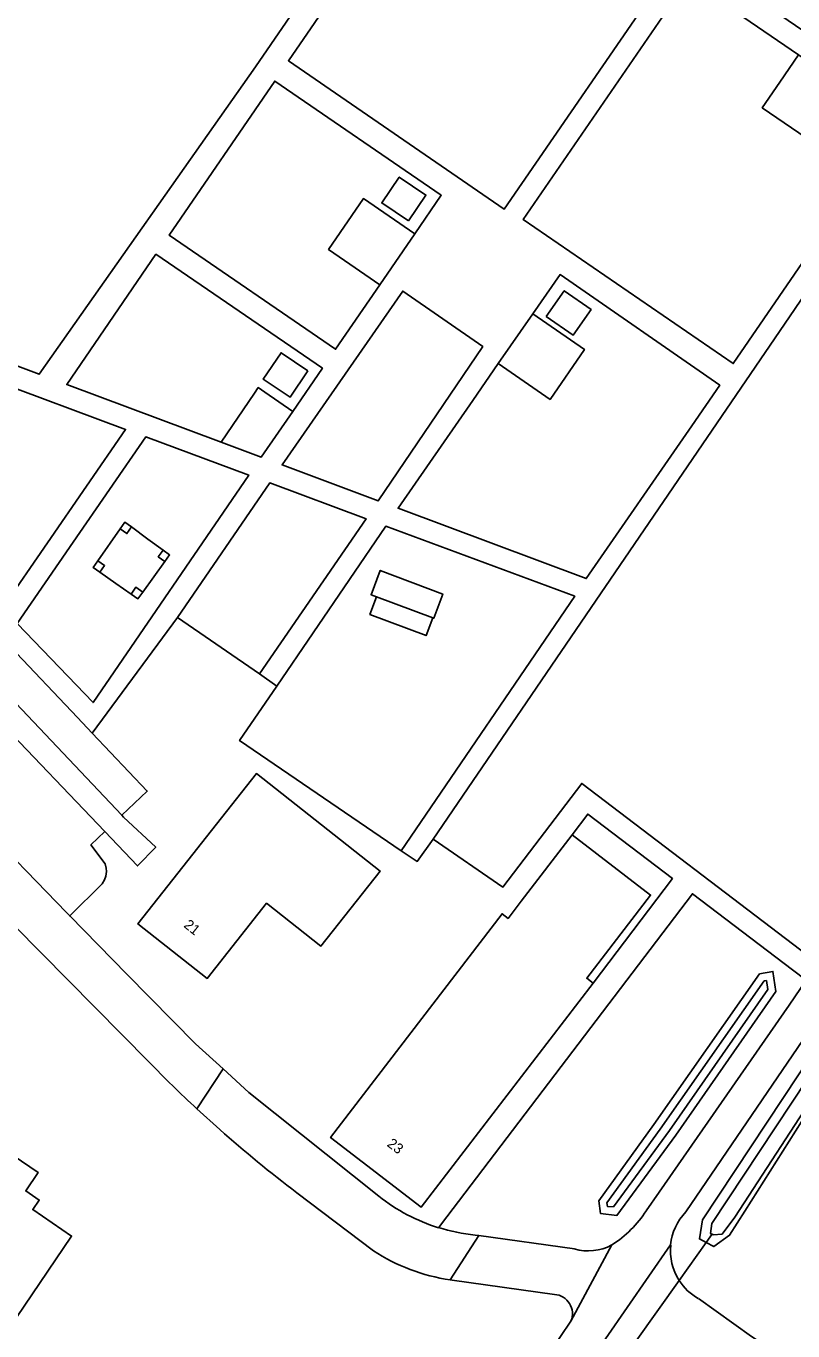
# Model space of a CAD drawing. Extents: x 158132 to 159664, y 385256 to 387218.
# Drawn here: x 159204 to 159278.7, y 386123.9 to 386251 of the extents above; entities that cross this region are included whole.
import ezdxf

# ---------------------------------------------------------------- set-up
doc = ezdxf.new("R2010")
doc.units = 0
for name, color, linetype in [('IMGEO_Berm_groen', 7, 'Continuous'), ('IMGEO_Duiker', 7, 'Continuous'), ('IMGEO_Erf', 7, 'Continuous'), ('IMGEO_Grasland_overig', 7, 'Continuous'), ('IMGEO_Groenvoorziening', 7, 'Continuous'), ('IMGEO_Hoogspanningsmast', 7, 'Continuous'), ('IMGEO_Oever', 7, 'Continuous'), ('IMGEO_Pand', 7, 'Continuous'), ('IMGEO_Pand_nummerreeks', 7, 'Continuous'), ('IMGEO_Rijbaan_lokaal_gesloten', 7, 'Continuous'), ('IMGEO_Rijbaan_lokaal_open', 7, 'Continuous'), ('IMGEO_Terreindeel_zand', 7, 'Continuous'), ('IMGEO_Voetpad_gesloten', 7, 'Continuous'), ('IMGEO_Voetpad_onverhard', 7, 'Continuous'), ('IMGEO_Voetpad_open', 7, 'Continuous'), ('IMGEO_Waterloop', 7, 'Continuous')]:
    doc.layers.add(name, color=color, linetype=linetype)

msp = doc.modelspace()

# ---------------------------------------------------------------- linework, layer by layer
at = {"layer": 'IMGEO_Berm_groen'}
msp.add_lwpolyline([(159199.08, 386173.74), (159207.91, 386164.65), (159208.23, 386164.33), (159211.4, 386167.46), (159211.62, 386167.84), (159211.76, 386168.21), (159211.81, 386168.66), (159211.78, 386168.98), (159211.7, 386169.41), (159210.3, 386171.26), (159211.64, 386172.54), (159201.25, 386183.41)], dxfattribs=at)
at = {"layer": 'IMGEO_Duiker'}
msp.add_lwpolyline([(159261.44, 386120.14), (159261.9, 386120.78), (159263.43, 386122.94), (159267.62, 386128.82), (159270.25, 386132.52), (159270.87, 386133.39)], dxfattribs=at)
at = {"layer": 'IMGEO_Erf'}
for points in [[(159189.36, 386204.31), (159190.4, 386205.83), (159184.95, 386209.75), (159191.94, 386219.49), (159197.15, 386215.75), (159198.3, 386217.43), (159196.94, 386217.94), (159191.1, 386220.11), (159182.08, 386207.11), (159185.76, 386203.21), (159213.3, 386174.13), (159215.79, 386176.48), (159210.43, 386182.12), (159208.99, 386183.64)], [(159257.45, 386195.47), (159239.05, 386202.31), (159228.41, 386186.71), (159224.79, 386181.41), (159240.54, 386170.67)], [(159238.13, 386195.42), (159237.6, 386195.62), (159238.49, 386197.98), (159244.59, 386195.68), (159243.7, 386193.32), (159243.61, 386193.35), (159242.96, 386191.63), (159237.48, 386193.7)], [(159257.19, 386172.23), (159264.84, 386166.36), (159258.61, 386158.25), (159259.23, 386157.78), (159266.97, 386167.97), (159258.72, 386174.24)]]:
    msp.add_lwpolyline(points, close=True, dxfattribs=at)
for points in [[(159215.95, 386150.12), (159194.97, 386171.32), (159186.76, 386179.61), (159163.78, 386202.2), (159162.52, 386201.03), (159161.57, 386199.27), (159161.76, 386197.29), (159157.91, 386193.34), (159157.34, 386195.65), (159156.59, 386198.71), (159154.11, 386200.88)], [(159222.86, 386143.51), (159220.62, 386145.54)], [(159200.96, 386142.17), (159205.17, 386139.33), (159203.95, 386137.53), (159205.26, 386136.65), (159204.63, 386135.72), (159208.42, 386133.13), (159197.66, 386117.28)], [(159237.83, 386131.71), (159230.36, 386137.36)], [(159255.48, 386127.45), (159245.5, 386128.84), (159245.31, 386128.87)], [(159229.89, 386084.81), (159246.98, 386109.91), (159257.08, 386124.85)]]:
    msp.add_lwpolyline(points, dxfattribs=at)
for centre, radius, start, end in [((159306.32, 386237.61), 125.79, 224.0718, 227.0544), ((159306.29, 386237.66), 125.8, 228.4531, 232.8708), ((159248.09, 386147.46), 18.8, 236.8955, 261.4899), ((159255.33, 386125.57), 1.89, 337.5539, 85.5579)]:
    msp.add_arc(centre, radius, start, end, dxfattribs=at)
at = {"layer": 'IMGEO_Grasland_overig'}
msp.add_lwpolyline([(159217.33, 386199.96), (159215.85, 386201.04), (159214.26, 386202.22), (159213.81, 386201.58), (159213.15, 386202.03), (159210.97, 386198.92), (159211.63, 386198.46), (159211.17, 386197.8), (159212.74, 386196.71), (159214.21, 386195.68), (159214.67, 386196.34), (159215.34, 386195.88), (159217.5, 386198.84), (159216.86, 386199.32)], close=True, dxfattribs=at)
at = {"layer": 'IMGEO_Groenvoorziening'}
for points in [[(159197.51, 386219.99), (159205.27, 386217.09), (159226.34, 386247.04), (159245.05, 386274.31)], [(159289.4, 386252.35), (159285.49, 386246.62), (159291.76, 386242.35), (159277.87, 386221.99), (159260.44, 386196.43), (159243.64, 386171.79), (159250.45, 386167.14), (159258.12, 386177.23), (159279.47, 386161), (159281.13, 386159.74), (159298.47, 386185.36), (159324.83, 386224.2), (159336.01, 386241.27), (159336.74, 386243.4), (159337.22, 386246.5), (159337.54, 386249.36), (159337.73, 386249.49), (159337.39, 386250), (159335.51, 386252.86)], [(159339.02, 386239.61), (159327.47, 386222.89), (159301.01, 386183.54), (159268.27, 386135.49)], [(159278.35, 386155.63), (159280, 386158.07), (159278.67, 386159.08), (159268.92, 386166.49), (159244.99, 386135.02), (159244.18, 386133.95)], [(159264.42, 386135.61), (159265.68, 386137.43), (159278.35, 386155.63)], [(159247.75, 386133.23), (159248.11, 386133.18), (159257.41, 386131.88)], [(159269.49, 386127.04), (159274.68, 386123.36), (159277.5, 386121.54)]]:
    msp.add_lwpolyline(points, dxfattribs=at)
for points in [[(159266.7, 386256.67), (159255.03, 386264.68), (159252.37, 386260.81), (159251.52, 386259.55), (159246.52, 386262.98), (159250.03, 386268.1), (159245.65, 386271.11), (159229.54, 386247.63), (159250.58, 386233.19)], [(159288.95, 386241.54), (159284.24, 386244.78), (159283.76, 386244.09), (159280.71, 386239.63), (159275.71, 386243.05), (159277.42, 386245.54), (159279.24, 386248.2), (159268.5, 386255.58), (159252.43, 386232.16), (159272.89, 386218.13)], [(159274.02, 386135.57), (159272.53, 386133.21), (159271, 386132.12), (159270.25, 386132.52), (159269.6, 386132.86), (159269.89, 386134.71), (159282.42, 386153.64), (159285.72, 386158.2), (159313.98, 386199.88), (159331.21, 386225.47), (159339.73, 386238.63), (159341.89, 386239.72), (159342.68, 386239.03), (159342.6, 386237.83), (159333.22, 386224.3), (159322.06, 386207.96), (159316.15, 386199.14), (159313.78, 386195.47), (159287.98, 386156.98), (159284.5, 386152.12)], [(159232.86, 386217.68), (159216.63, 386228.79), (159207.94, 386216.09), (159222.98, 386210.48), (159226.24, 386215.25), (159226.61, 386215.79), (159227.25, 386215.34), (159229.96, 386213.47)], [(159271.57, 386216.03), (159256.01, 386226.81), (159253.36, 386222.98), (159258.39, 386219.51), (159255.04, 386214.65), (159249.99, 386218.13), (159247.5, 386214.53), (159240.23, 386204.04), (159258.56, 386197.19), (159268.84, 386212.08)], [(159248.48, 386219.79), (159240.69, 386225.19), (159228.92, 386208.26), (159238.3, 386204.76)], [(159254.67, 386222.73), (159256.42, 386225.23), (159259.04, 386223.39), (159257.29, 386220.89)], [(159231.43, 386217.44), (159229.7, 386214.86), (159227.09, 386216.61), (159228.83, 386219.19)], [(159201.67, 386194.32), (159206.05, 386200.66), (159213.68, 386211.72), (159200.4, 386216.65), (159192.02, 386204.39)], [(159225.68, 386207.27), (159215.64, 386210.99), (159208.56, 386200.73), (159203.11, 386192.82), (159210.51, 386185.11)], [(159227.72, 386206.51), (159218.75, 386193.4), (159226.74, 386187.91), (159237.11, 386203.02)], [(159217.33, 386199.96), (159217.97, 386199.49), (159217.5, 386198.84), (159215.34, 386195.88), (159214.87, 386195.23), (159214.21, 386195.68), (159212.74, 386196.71), (159211.17, 386197.8), (159210.52, 386198.26), (159210.97, 386198.92), (159213.15, 386202.03), (159213.61, 386202.69), (159214.26, 386202.22), (159215.85, 386201.04)], [(159275.46, 386158.69), (159276.76, 386158.92), (159277.05, 386156.96), (159267.3, 386142.98), (159261.56, 386135.15), (159259.95, 386135.34), (159259.78, 386136.58), (159265.14, 386144.01)]]:
    msp.add_lwpolyline(points, close=True, dxfattribs=at)
for centre, radius, start, end in [((159255.04, 386141.71), 11.19, 302.5146, 326.9899), ((159272.16, 386131.75), 5.4, 136.1105, 174.4294), ((159249.49, 386151.04), 17.89, 252.7239, 264.4032), ((159258.75, 386136.51), 4.82, 253.7845, 298.4953), ((159272.17, 386131.74), 5.4, 174.4016, 212.723), ((159272.17, 386131.74), 5.41, 212.6646, 240.2585)]:
    msp.add_arc(centre, radius, start, end, dxfattribs=at)
at = {"layer": 'IMGEO_Hoogspanningsmast'}
for points in [[(159214.26, 386202.22), (159213.61, 386202.69), (159213.15, 386202.03), (159213.81, 386201.58)], [(159217.97, 386199.49), (159217.33, 386199.96), (159216.86, 386199.32), (159217.5, 386198.84)], [(159210.97, 386198.92), (159210.52, 386198.26), (159211.17, 386197.8), (159211.63, 386198.46)], [(159215.34, 386195.88), (159214.67, 386196.34), (159214.21, 386195.68), (159214.87, 386195.23)]]:
    msp.add_lwpolyline(points, close=True, dxfattribs=at)
at = {"layer": 'IMGEO_Oever'}
for points in [[(159333.22, 386224.3), (159342.6, 386237.83), (159342.68, 386239.03), (159341.89, 386239.72), (159339.73, 386238.63), (159331.21, 386225.47), (159313.98, 386199.88), (159285.72, 386158.2), (159282.42, 386153.64), (159269.89, 386134.71), (159269.6, 386132.86), (159270.25, 386132.52), (159271, 386132.12), (159272.53, 386133.21), (159274.02, 386135.57), (159284.5, 386152.12), (159287.98, 386156.98), (159313.78, 386195.47), (159316.15, 386199.14), (159322.06, 386207.96)], [(159270.92, 386133.25), (159270.81, 386133.31), (159270.7, 386133.37), (159270.66, 386133.39), (159270.82, 386134.35), (159283.21, 386153.09), (159286.51, 386157.65), (159296.19, 386171.93), (159296.61, 386172.54), (159314.78, 386199.34), (159332.01, 386224.94), (159340.4, 386237.89), (159341.31, 386238.85), (159341.72, 386238.92), (159342.06, 386238.68), (159342.11, 386237.96), (159334.58, 386227.11), (159311.12, 386192.09), (159297.57, 386171.9), (159297.15, 386171.28), (159281.59, 386148.1), (159273.05, 386134.97), (159271.81, 386133.32)], [(159267.3, 386142.98), (159277.05, 386156.96), (159276.76, 386158.92), (159275.46, 386158.69), (159265.14, 386144.01), (159259.78, 386136.58), (159259.95, 386135.34), (159261.56, 386135.15)], [(159275.91, 386157.99), (159276.12, 386158.03), (159276.25, 386157.15), (159266.67, 386143.43), (159261.21, 386135.97), (159260.63, 386136.03), (159260.58, 386136.38), (159265.77, 386143.56)]]:
    msp.add_lwpolyline(points, close=True, dxfattribs=at)
at = {"layer": 'IMGEO_Pand'}
for points in [[(159241.25, 386232.03), (159242.95, 386234.55), (159240.34, 386236.31), (159238.64, 386233.78)], [(159254.67, 386222.73), (159257.29, 386220.89), (159259.04, 386223.39), (159256.42, 386225.23)], [(159231.43, 386217.44), (159228.83, 386219.19), (159227.09, 386216.61), (159229.7, 386214.86)], [(159238.49, 386197.98), (159237.6, 386195.62), (159238.13, 386195.42), (159243.61, 386193.35), (159243.7, 386193.32), (159244.59, 386195.68)], [(159243.61, 386193.35), (159238.13, 386195.42), (159237.48, 386193.7), (159242.96, 386191.63)], [(159221.63, 386158.23), (159227.41, 386165.56), (159232.71, 386161.38), (159238.47, 386168.69), (159226.42, 386178.19), (159214.88, 386163.55)], [(159259.23, 386157.78), (159258.61, 386158.25), (159264.84, 386166.36), (159257.19, 386172.23), (159252.24, 386165.77), (159250.95, 386164.09), (159250.37, 386164.53), (159233.66, 386142.73), (159242.49, 386135.96)]]:
    msp.add_lwpolyline(points, close=True, dxfattribs=at)
msp.add_lwpolyline([(159197.66, 386117.28), (159208.42, 386133.13), (159204.63, 386135.72), (159205.26, 386136.65), (159203.95, 386137.53), (159205.17, 386139.33), (159200.96, 386142.17)], dxfattribs=at)
at = {"layer": 'IMGEO_Rijbaan_lokaal_gesloten'}
for points in [[(159341.65, 386240.97), (159343.21, 386240.87), (159337.73, 386249.49), (159337.54, 386249.36), (159337.22, 386246.5), (159336.74, 386243.4), (159336.01, 386241.27), (159324.83, 386224.2), (159298.47, 386185.36), (159281.13, 386159.74), (159280, 386158.07), (159278.35, 386155.63), (159265.68, 386137.43), (159264.42, 386135.61)], [(159268.27, 386135.49), (159301.01, 386183.54), (159327.47, 386222.89), (159339.02, 386239.61)], [(159220.48, 386151.86), (159213.8, 386158.66), (159208.23, 386164.33), (159207.91, 386164.65), (159199.08, 386173.74), (159197.66, 386175.17), (159194.19, 386178.66), (159166.55, 386206.55), (159166.05, 386207.2), (159165.58, 386207.94), (159165.17, 386208.71), (159164.84, 386209.52), (159164.58, 386210.36), (159164.39, 386211.21), (159164.27, 386212.08), (159164.24, 386212.96), (159164.28, 386213.83), (159164.39, 386214.7), (159164.59, 386215.56), (159164.85, 386216.39), (159165.19, 386217.2), (159165.49, 386217.77), (159165.6, 386217.98), (159152.42, 386199.12)], [(159163.18, 386202.58), (159163.78, 386202.2), (159186.76, 386179.61), (159194.97, 386171.32), (159215.95, 386150.12)], [(159220.62, 386145.54), (159223.17, 386149.42), (159220.48, 386151.86)], [(159257.41, 386131.88), (159248.11, 386133.18), (159245.31, 386128.87), (159245.5, 386128.84), (159255.48, 386127.45)], [(159261.05, 386132.27), (159257.08, 386124.85), (159246.98, 386109.91), (159229.89, 386084.81), (159194.42, 386031.4), (159183.73, 386016.54), (159182.09, 386014.12), (159184.96, 386012.05), (159184.98, 386012.08), (159204.57, 386041.21)], [(159204.57, 386041.21), (159249.31, 386107.22), (159258.33, 386120.06), (159266.79, 386132.27)], [(159257.08, 386124.85), (159261.05, 386132.27)], [(159266.79, 386132.27), (159258.33, 386120.06)], [(159277.5, 386121.54), (159274.68, 386123.36), (159269.49, 386127.04)]]:
    msp.add_lwpolyline(points, dxfattribs=at)
for centre, radius, start, end in [((159306.32, 386237.61), 125.79, 224.0718, 227.0544), ((159255.04, 386141.71), 11.19, 302.5146, 326.9899), ((159272.16, 386131.75), 5.4, 136.1105, 174.4294), ((159258.75, 386136.51), 4.82, 253.7845, 298.4953), ((159272.17, 386131.74), 5.4, 174.4016, 212.723), ((159272.17, 386131.74), 5.41, 212.6646, 240.2585), ((159255.33, 386125.57), 1.89, 337.5539, 85.5579)]:
    msp.add_arc(centre, radius, start, end, dxfattribs=at)
at = {"layer": 'IMGEO_Rijbaan_lokaal_open'}
for points in [[(159225.69, 386147.14), (159223.17, 386149.42), (159220.62, 386145.54), (159222.86, 386143.51)], [(159238.35, 386137.03), (159225.69, 386147.14)], [(159230.36, 386137.36), (159237.83, 386131.71)], [(159245.31, 386128.87), (159248.11, 386133.18), (159247.75, 386133.23)]]:
    msp.add_lwpolyline(points, dxfattribs=at)
for centre, radius, start, end in [((159306.29, 386237.66), 125.8, 228.4531, 232.8708), ((159249.5, 386151.08), 17.94, 231.5483, 252.751), ((159249.49, 386151.04), 17.89, 252.7239, 264.4032), ((159248.09, 386147.46), 18.8, 236.8955, 261.4899)]:
    msp.add_arc(centre, radius, start, end, dxfattribs=at)
at = {"layer": 'IMGEO_Terreindeel_zand'}
for points in [[(159236.85, 386234.21), (159241.86, 386230.77), (159244.43, 386234.53), (159228.21, 386245.66), (159217.92, 386230.66), (159234.14, 386219.53), (159238.46, 386225.82), (159235.54, 386227.83), (159233.45, 386229.26)], [(159241.25, 386232.03), (159238.64, 386233.78), (159240.34, 386236.31), (159242.95, 386234.55)]]:
    msp.add_lwpolyline(points, close=True, dxfattribs=at)
at = {"layer": 'IMGEO_Voetpad_gesloten'}
for points in [[(159284.24, 386244.78), (159279.24, 386248.2), (159277.42, 386245.54), (159275.71, 386243.05), (159280.71, 386239.63), (159283.76, 386244.09)], [(159241.86, 386230.77), (159236.85, 386234.21), (159233.45, 386229.26), (159235.54, 386227.83), (159238.46, 386225.82)], [(159253.36, 386222.98), (159249.99, 386218.13), (159255.04, 386214.65), (159258.39, 386219.51)]]:
    msp.add_lwpolyline(points, close=True, dxfattribs=at)
at = {"layer": 'IMGEO_Voetpad_onverhard'}
for points in [[(159245.05, 386274.31), (159226.34, 386247.04), (159205.27, 386217.09), (159197.51, 386219.99)], [(159189.36, 386204.31), (159208.99, 386183.64), (159210.43, 386182.12), (159218.75, 386193.4), (159227.72, 386206.51), (159237.11, 386203.02), (159226.74, 386187.91), (159228.41, 386186.71), (159239.05, 386202.31), (159257.45, 386195.47), (159240.54, 386170.67), (159242.09, 386169.63), (159243.64, 386171.79), (159260.44, 386196.43), (159277.87, 386221.99), (159291.76, 386242.35), (159285.49, 386246.62), (159280.5, 386250.03), (159269.89, 386257.27)]]:
    msp.add_lwpolyline(points, dxfattribs=at)
for points in [[(159229.54, 386247.63), (159245.65, 386271.11), (159250.03, 386268.1), (159255.03, 386264.68), (159266.7, 386256.67), (159250.58, 386233.19)], [(159268.5, 386255.58), (159279.24, 386248.2), (159284.24, 386244.78), (159288.95, 386241.54), (159272.89, 386218.13), (159252.43, 386232.16)], [(159217.92, 386230.66), (159228.21, 386245.66), (159244.43, 386234.53), (159241.86, 386230.77), (159238.46, 386225.82), (159234.14, 386219.53)], [(159207.94, 386216.09), (159216.63, 386228.79), (159232.86, 386217.68), (159229.96, 386213.47), (159226.89, 386209.02), (159222.98, 386210.48)], [(159247.5, 386214.53), (159249.99, 386218.13), (159253.36, 386222.98), (159256.01, 386226.81), (159271.57, 386216.03), (159268.84, 386212.08), (159258.56, 386197.19), (159240.23, 386204.04)], [(159228.92, 386208.26), (159240.69, 386225.19), (159248.48, 386219.79), (159238.3, 386204.76)], [(159201.67, 386194.32), (159192.02, 386204.39), (159200.4, 386216.65), (159213.68, 386211.72), (159206.05, 386200.66)], [(159229.96, 386213.47), (159227.25, 386215.34), (159226.61, 386215.79), (159226.24, 386215.25), (159222.98, 386210.48), (159226.89, 386209.02)], [(159208.56, 386200.73), (159215.64, 386210.99), (159225.68, 386207.27), (159210.51, 386185.11), (159203.11, 386192.82)]]:
    msp.add_lwpolyline(points, close=True, dxfattribs=at)
at = {"layer": 'IMGEO_Voetpad_open'}
for points in [[(159185.76, 386203.21), (159182.08, 386207.11), (159180.77, 386208.48), (159168.24, 386221.73), (159166.79, 386219.66), (159186.56, 386198.75), (159201.25, 386183.41), (159211.64, 386172.54), (159214.83, 386169.2), (159216.62, 386171.01), (159213.48, 386173.94), (159213.3, 386174.13)], [(159232.71, 386161.38), (159227.41, 386165.56), (159221.63, 386158.23), (159214.88, 386163.55), (159226.42, 386178.19), (159238.47, 386168.69)], [(159250.37, 386164.53), (159250.95, 386164.09), (159252.24, 386165.77), (159257.19, 386172.23), (159258.72, 386174.24), (159266.97, 386167.97), (159259.23, 386157.78), (159242.49, 386135.96), (159233.66, 386142.73)]]:
    msp.add_lwpolyline(points, close=True, dxfattribs=at)
for points in [[(159279.47, 386161), (159258.12, 386177.23), (159250.45, 386167.14), (159243.64, 386171.79), (159242.09, 386169.63), (159240.54, 386170.67), (159224.79, 386181.41), (159228.41, 386186.71), (159226.74, 386187.91), (159218.75, 386193.4), (159210.43, 386182.12), (159215.79, 386176.48), (159213.3, 386174.13), (159213.48, 386173.94), (159216.62, 386171.01), (159214.83, 386169.2), (159211.64, 386172.54), (159210.3, 386171.26), (159211.7, 386169.41), (159211.78, 386168.98), (159211.81, 386168.66), (159211.76, 386168.21), (159211.62, 386167.84), (159211.4, 386167.46), (159208.23, 386164.33), (159213.8, 386158.66), (159220.48, 386151.86), (159223.17, 386149.42), (159225.69, 386147.14), (159238.35, 386137.03)], [(159244.18, 386133.95), (159244.99, 386135.02), (159268.92, 386166.49)], [(159268.92, 386166.49), (159278.67, 386159.08), (159280, 386158.07)]]:
    msp.add_lwpolyline(points, dxfattribs=at)
msp.add_arc((159249.5, 386151.08), 17.94, 231.5483, 252.751, dxfattribs=at)
at = {"layer": 'IMGEO_Waterloop'}
for points in [[(159270.92, 386133.25), (159271.81, 386133.32), (159273.05, 386134.97), (159281.59, 386148.1), (159297.15, 386171.28), (159297.57, 386171.9), (159311.12, 386192.09), (159334.58, 386227.11), (159342.11, 386237.96), (159342.06, 386238.68), (159341.72, 386238.92), (159341.31, 386238.85), (159340.4, 386237.89), (159332.01, 386224.94), (159314.78, 386199.34), (159296.61, 386172.54), (159296.19, 386171.93), (159286.51, 386157.65), (159283.21, 386153.09), (159270.82, 386134.35), (159270.66, 386133.39), (159270.7, 386133.37), (159270.81, 386133.31)], [(159275.91, 386157.99), (159265.77, 386143.56), (159260.58, 386136.38), (159260.63, 386136.03), (159261.21, 386135.97), (159266.67, 386143.43), (159276.25, 386157.15), (159276.12, 386158.03)]]:
    msp.add_lwpolyline(points, close=True, dxfattribs=at)

# ---------------------------------------------------------------- texts
at = {"layer": 'IMGEO_Pand_nummerreeks'}
for s, rotation, p in [('21', 321.2531, (159219.27, 386163.3)), ('23', 322.901, (159239.08, 386141.96))]:
    msp.add_text(s, height=1, rotation=rotation, dxfattribs=at).set_placement(p)

doc.saveas('drawing.dxf')
